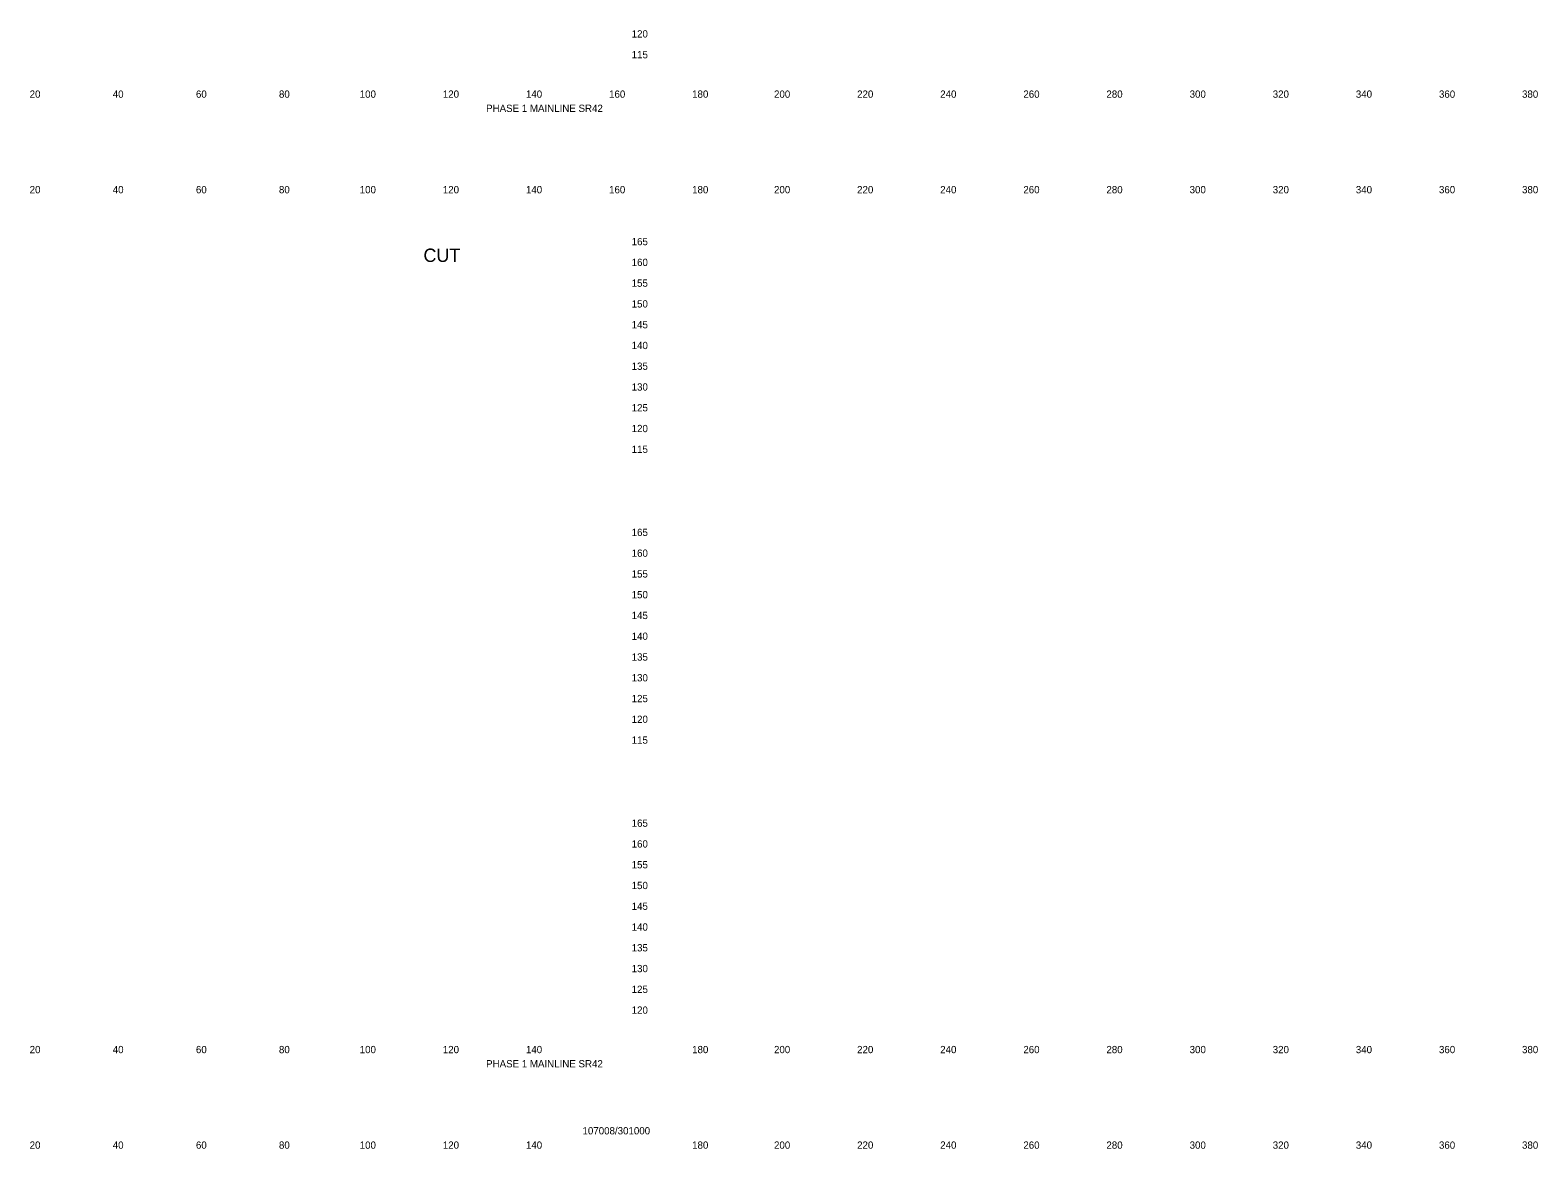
# Model space of a CAD drawing. Extents: x 21281 to 22024, y 6472 to 15198.
# Drawn here: x 21661.4 to 22024.2, y 7832.3 to 8101.6 of the extents above; entities that cross this region are included whole.
import ezdxf

# ---------------------------------------------------------------- set-up
doc = ezdxf.new("R2010")
doc.units = 0
doc.layers.add('XS_SHEET_LABELS_ELEVATION', color=7, linetype='Continuous')
doc.layers.add('XS_SHEET_LABELS_OFFSET', color=7, linetype='Continuous')

msp = doc.modelspace()

# ---------------------------------------------------------------- texts
at = {"layer": 'XS_SHEET_LABELS_ELEVATION'}
for s, p in [('  120  ', (21804.84, 8099.84)), ('  115  ', (21804.84, 8094.84)), ('  165  ', (21804.84, 8049.84)), ('  160  ', (21804.84, 8044.84)), ('  155  ', (21804.84, 8039.84)), ('  150  ', (21804.84, 8034.84)), ('  145  ', (21804.84, 8029.84)), ('  140  ', (21804.84, 8024.84)), ('  135  ', (21804.84, 8019.84)), ('  130  ', (21804.84, 8014.84)), ('  125  ', (21804.84, 8009.84)), ('  120  ', (21804.84, 8004.84)), ('  115  ', (21804.84, 7999.84)), ('  165  ', (21804.84, 7979.84)), ('  160  ', (21804.84, 7974.84)), ('  155  ', (21804.84, 7969.84)), ('  150  ', (21804.84, 7964.84)), ('  145  ', (21804.84, 7959.84)), ('  140  ', (21804.84, 7954.84)), ('  135  ', (21804.84, 7949.84)), ('  130  ', (21804.84, 7944.84)), ('  125  ', (21804.84, 7939.84)), ('  120  ', (21804.84, 7934.84)), ('  115  ', (21804.84, 7929.84)), ('  165  ', (21804.84, 7909.84)), ('  160  ', (21804.84, 7904.84)), ('  155  ', (21804.84, 7899.84)), ('  150  ', (21804.84, 7894.84)), ('  145  ', (21804.84, 7889.84)), ('  140  ', (21804.84, 7884.84)), ('  135  ', (21804.84, 7879.84)), ('  130  ', (21804.84, 7874.84)), ('  125  ', (21804.84, 7869.84)), ('  120  ', (21804.84, 7864.84))]:
    msp.add_text(s, height=1.75, dxfattribs=at).set_placement(p)
at = {"layer": 'XS_SHEET_LABELS_OFFSET'}
for s, height, p in [('  20  ', 1.75, (21659.95, 8085.34)), ('  40  ', 1.75, (21679.95, 8085.34)), ('  60  ', 1.75, (21699.97, 8085.34)), ('  80  ', 1.75, (21719.95, 8085.34)), ('  100  ', 1.75, (21739.39, 8085.34)), ('  120  ', 1.75, (21759.39, 8085.34)), ('  140  ', 1.75, (21779.39, 8085.34)), ('  160  ', 1.75, (21799.4, 8085.34)), ('  180  ', 1.75, (21819.39, 8085.34)), ('  200  ', 1.75, (21839.1, 8085.34)), ('  220  ', 1.75, (21859.1, 8085.34)), ('  240  ', 1.75, (21879.1, 8085.34)), ('  260  ', 1.75, (21899.11, 8085.34)), ('  280  ', 1.75, (21919.1, 8085.34)), ('  300  ', 1.75, (21939.13, 8085.34)), ('  320  ', 1.75, (21959.13, 8085.34)), ('  340  ', 1.75, (21979.13, 8085.34)), ('  360  ', 1.75, (21999.14, 8085.34)), ('  380  ', 1.75, (22019.13, 8085.34)), ('PHASE 1 MAINLINE SR42', 1.75, (21771.11, 8081.92)), ('  20  ', 1.75, (21659.95, 8062.34)), ('  40  ', 1.75, (21679.95, 8062.34)), ('  60  ', 1.75, (21699.97, 8062.34)), ('  80  ', 1.75, (21719.95, 8062.34)), ('  100  ', 1.75, (21739.39, 8062.34)), ('  120  ', 1.75, (21759.39, 8062.34)), ('  140  ', 1.75, (21779.39, 8062.34)), ('  160  ', 1.75, (21799.4, 8062.34)), ('  180  ', 1.75, (21819.39, 8062.34)), ('  200  ', 1.75, (21839.1, 8062.34)), ('  220  ', 1.75, (21859.1, 8062.34)), ('  240  ', 1.75, (21879.1, 8062.34)), ('  260  ', 1.75, (21899.11, 8062.34)), ('  280  ', 1.75, (21919.1, 8062.34)), ('  300  ', 1.75, (21939.13, 8062.34)), ('  320  ', 1.75, (21959.13, 8062.34)), ('  340  ', 1.75, (21979.13, 8062.34)), ('  360  ', 1.75, (21999.14, 8062.34)), ('  380  ', 1.75, (22019.13, 8062.34)), ('CUT', 3.222, (21756.03, 8045.81)), ('  20  ', 1.75, (21659.95, 7855.34)), ('  40  ', 1.75, (21679.95, 7855.34)), ('  60  ', 1.75, (21699.97, 7855.34)), ('  80  ', 1.75, (21719.95, 7855.34)), ('  100  ', 1.75, (21739.39, 7855.34)), ('  120  ', 1.75, (21759.39, 7855.34)), ('  140  ', 1.75, (21779.39, 7855.34)), ('  180  ', 1.75, (21819.39, 7855.34)), ('  200  ', 1.75, (21839.1, 7855.34)), ('  220  ', 1.75, (21859.1, 7855.34)), ('  240  ', 1.75, (21879.1, 7855.34)), ('  260  ', 1.75, (21899.11, 7855.34)), ('  280  ', 1.75, (21919.1, 7855.34)), ('  300  ', 1.75, (21939.13, 7855.34)), ('  320  ', 1.75, (21959.13, 7855.34)), ('  340  ', 1.75, (21979.13, 7855.34)), ('  360  ', 1.75, (21999.14, 7855.34)), ('  380  ', 1.75, (22019.13, 7855.34)), ('PHASE 1 MAINLINE SR42', 1.75, (21771.11, 7851.92)), ('107008/301000', 1.75, (21794.31, 7835.79)), ('  20  ', 1.75, (21659.95, 7832.34)), ('  40  ', 1.75, (21679.95, 7832.34)), ('  60  ', 1.75, (21699.97, 7832.34)), ('  80  ', 1.75, (21719.95, 7832.34)), ('  100  ', 1.75, (21739.39, 7832.34)), ('  120  ', 1.75, (21759.39, 7832.34)), ('  140  ', 1.75, (21779.39, 7832.34)), ('  180  ', 1.75, (21819.39, 7832.34)), ('  200  ', 1.75, (21839.1, 7832.34)), ('  220  ', 1.75, (21859.1, 7832.34)), ('  240  ', 1.75, (21879.1, 7832.34)), ('  260  ', 1.75, (21899.11, 7832.34)), ('  280  ', 1.75, (21919.1, 7832.34)), ('  300  ', 1.75, (21939.13, 7832.34)), ('  320  ', 1.75, (21959.13, 7832.34)), ('  340  ', 1.75, (21979.13, 7832.34)), ('  360  ', 1.75, (21999.14, 7832.34)), ('  380  ', 1.75, (22019.13, 7832.34))]:
    msp.add_text(s, height=height, dxfattribs=at).set_placement(p)

doc.saveas('drawing.dxf')
